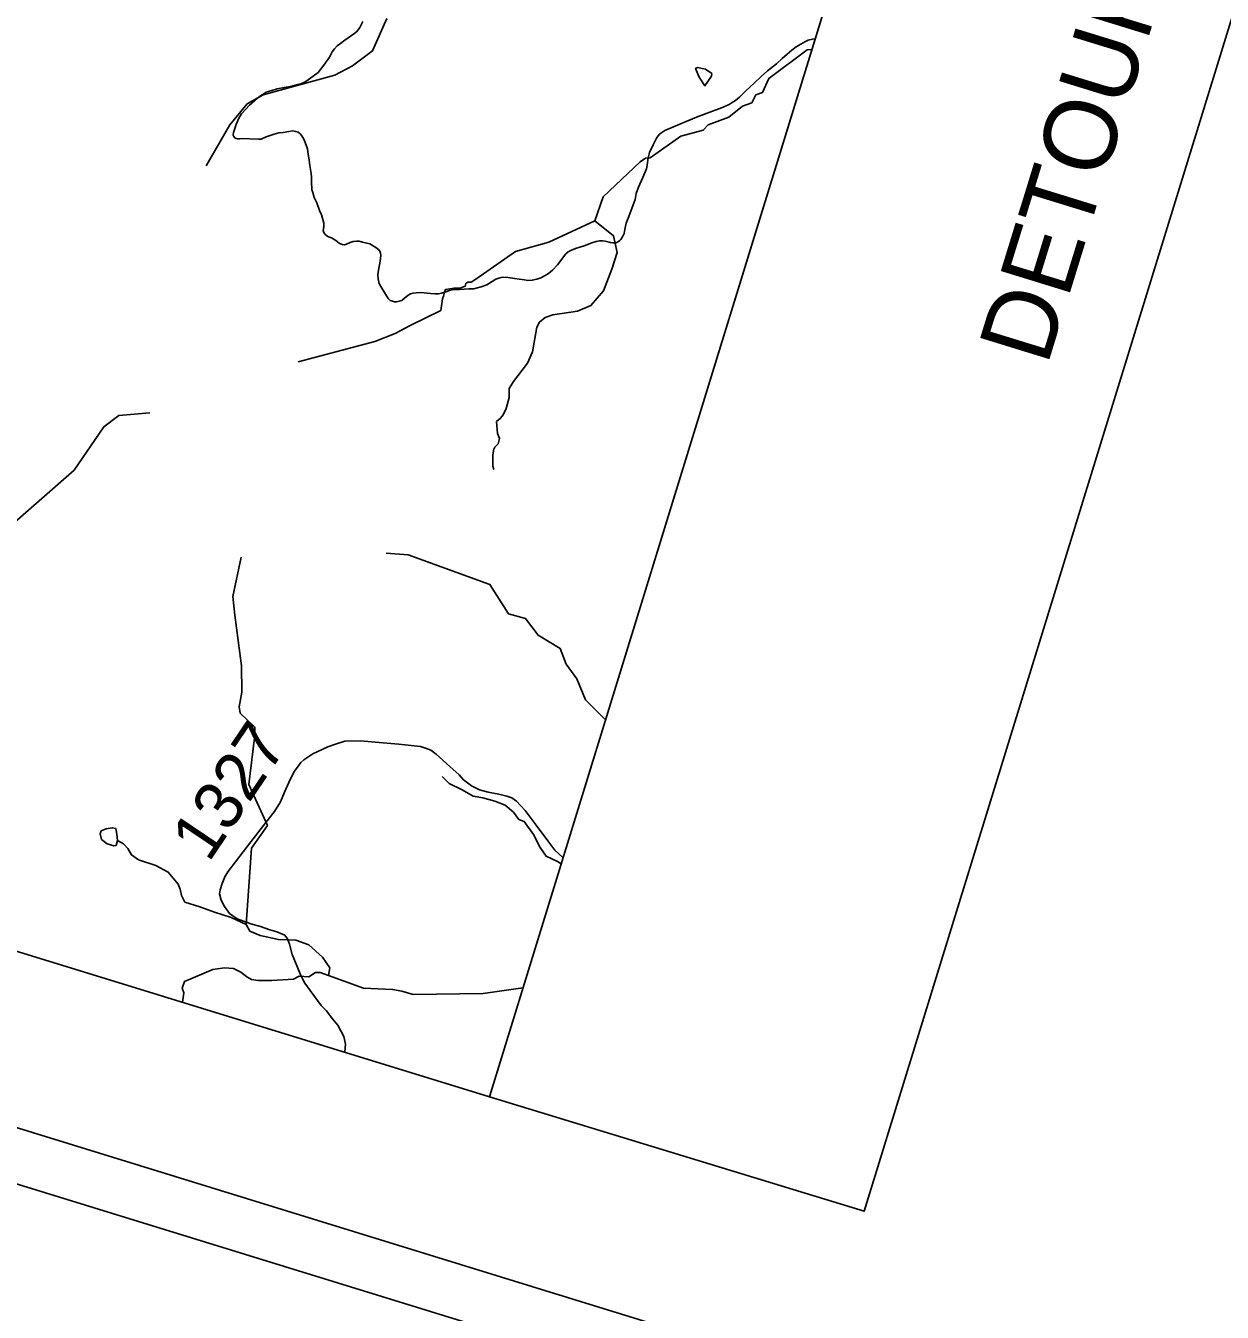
# Model space of a CAD drawing. Extents: x 1347947 to 1350662, y 1027710 to 1030532.
# Drawn here: x 1348242 to 1348353.5, y 1028682.4 to 1028802.3 of the extents above; entities that cross this region are included whole.
import ezdxf

# ---------------------------------------------------------------- set-up
doc = ezdxf.new("R2010")
doc.units = 0
for name, color, linetype in [('Default', 7, 'Continuous'), ('Prop Leader Line Light', 7, 'Continuous'), ('Prop WCC CELL', 7, 'Continuous'), ('Sheet Title CELL', 7, 'Continuous')]:
    doc.layers.add(name, color=color, linetype=linetype)

msp = doc.modelspace()

# ---------------------------------------------------------------- linework, layer by layer
at = {"layer": 'Default'}
msp.add_line((1348274.57, 1028772.86), (1348267.42, 1028770.97), dxfattribs=at)
for points in [[(1348258.85, 1028789.21), (1348261.05, 1028793.03), (1348262.68, 1028795.01), (1348264.17, 1028795.84), (1348270.83, 1028797.68), (1348272.49, 1028798.54), (1348274.35, 1028799.93), (1348275.67, 1028802.95)], [(1348273.43, 1028802.68), (1348273.17, 1028802.12), (1348272.92, 1028801.75), (1348272.71, 1028801.58), (1348271.76, 1028800.93), (1348271.37, 1028800.63), (1348271.06, 1028800.39), (1348270.8, 1028800.11), (1348270.6, 1028799.83), (1348270.33, 1028799.35), (1348269.8, 1028798.6), (1348269.27, 1028797.91), (1348268.49, 1028797.31), (1348268.24, 1028797.14), (1348267.89, 1028796.95), (1348267.66, 1028796.87), (1348267.36, 1028796.8), (1348266.71, 1028796.62), (1348266.13, 1028796.53), (1348265.48, 1028796.38), (1348264.89, 1028796.2), (1348264.44, 1028796.07), (1348264.08, 1028795.85), (1348263.82, 1028795.69), (1348263.38, 1028795.31), (1348262.9, 1028794.86), (1348262.15, 1028794.07), (1348261.88, 1028793.66), (1348261.65, 1028793.07), (1348261.4, 1028792.32), (1348261.37, 1028792.14), (1348261.38, 1028792.07), (1348261.44, 1028791.96), (1348261.52, 1028791.82), (1348261.63, 1028791.78), (1348261.76, 1028791.75), (1348261.98, 1028791.75)], [(1348296.39, 1028782.11), (1348296.48, 1028782.09), (1348296.74, 1028782.06), (1348297.04, 1028782.05), (1348297.27, 1028782.16), (1348297.39, 1028782.26), (1348297.47, 1028782.35), (1348297.65, 1028782.6), (1348297.78, 1028782.93), (1348297.86, 1028783.3), (1348297.9, 1028783.59), (1348297.98, 1028783.87), (1348298.22, 1028784.51), (1348298.64, 1028785.59), (1348298.8, 1028786.07), (1348298.91, 1028786.63), (1348299.14, 1028787.22), (1348299.54, 1028788.14), (1348299.88, 1028788.93), (1348299.94, 1028789.29), (1348300.04, 1028789.98), (1348300.15, 1028790.47), (1348300.49, 1028791.19), (1348300.81, 1028791.8), (1348301.04, 1028792.13), (1348301.29, 1028792.34), (1348301.58, 1028792.52), (1348302.39, 1028792.86), (1348303.58, 1028793.36), (1348304.54, 1028793.74), (1348305.77, 1028794.23), (1348306.87, 1028794.63), (1348307.57, 1028794.94), (1348307.86, 1028795.11), (1348308.16, 1028795.32), (1348308.53, 1028795.62), (1348309.11, 1028796.21), (1348309.89, 1028796.93), (1348310.54, 1028797.55), (1348311.14, 1028798.06), (1348311.98, 1028798.71), (1348312.52, 1028799.22), (1348312.96, 1028799.62), (1348313.41, 1028800), (1348313.82, 1028800.3), (1348314.26, 1028800.57), (1348314.68, 1028800.81), (1348314.94, 1028800.92), (1348315.32, 1028801.01), (1348315.58, 1028801.04)], [(1348315.28, 1028800.07), (1348314.83, 1028800.03), (1348311.27, 1028797.37), (1348310.69, 1028796.05), (1348310.06, 1028795.83), (1348309.67, 1028795.08), (1348308.82, 1028794.77), (1348307.53, 1028793.75), (1348305.63, 1028793.03), (1348305.14, 1028792.55), (1348303.08, 1028792), (1348300.22, 1028789.98), (1348299.79, 1028789.95), (1348299.28, 1028789.59), (1348295.83, 1028786.34), (1348295.05, 1028784.1), (1348290.78, 1028782.11), (1348287.67, 1028781.24), (1348283.96, 1028778.66), (1348283.53, 1028778.39), (1348283.22, 1028778.37), (1348283.04, 1028778.27), (1348282.98, 1028778.02), (1348282.58, 1028777.86), (1348281.95, 1028777.84), (1348281.14, 1028777.69), (1348281.04, 1028777.44)], [(1348305.92, 1028797.58), (1348305.32, 1028796.67), (1348304.77, 1028797.48), (1348304.44, 1028798.3), (1348304.62, 1028798.39), (1348305.37, 1028798.22), (1348305.96, 1028797.81), (1348305.92, 1028797.58)], [(1348305.92, 1028797.58), (1348305.32, 1028796.67), (1348304.77, 1028797.48), (1348304.44, 1028798.3), (1348304.62, 1028798.39), (1348305.37, 1028798.22), (1348305.96, 1028797.81), (1348305.92, 1028797.58)], [(1348261.98, 1028791.75), (1348262.28, 1028791.76), (1348262.92, 1028791.74), (1348263.75, 1028791.69), (1348263.98, 1028791.72), (1348264.45, 1028791.92), (1348265.17, 1028792.16), (1348265.61, 1028792.29), (1348266.01, 1028792.34), (1348266.54, 1028792.41), (1348266.89, 1028792.48), (1348267.2, 1028792.43), (1348267.42, 1028792.35), (1348267.62, 1028792.19), (1348267.77, 1028792.02), (1348267.96, 1028791.71), (1348268.08, 1028791.41), (1348268.29, 1028790.79), (1348268.34, 1028790.29), (1348268.45, 1028789.79), (1348268.49, 1028789.48), (1348268.51, 1028789.26), (1348268.63, 1028788.5), (1348268.65, 1028788.18), (1348268.67, 1028787.51), (1348268.7, 1028787.22), (1348268.68, 1028787), (1348268.79, 1028786.73), (1348268.91, 1028786.28), (1348269.17, 1028785.77), (1348269.4, 1028785.05), (1348269.59, 1028784.66), (1348269.73, 1028784.22), (1348269.81, 1028783.88), (1348269.82, 1028783.55), (1348269.75, 1028783.21), (1348269.77, 1028783.09), (1348269.85, 1028782.95), (1348270.01, 1028782.76), (1348270.24, 1028782.62), (1348270.53, 1028782.5), (1348270.85, 1028782.32), (1348271.05, 1028782.18), (1348271.28, 1028781.98), (1348271.56, 1028781.88), (1348271.73, 1028781.86), (1348271.92, 1028781.91), (1348272.26, 1028782.09), (1348272.56, 1028782.17), (1348272.85, 1028782.19), (1348273.09, 1028782.19), (1348273.42, 1028782.12), (1348274.09, 1028781.94), (1348274.66, 1028781.61), (1348274.91, 1028781.42), (1348275.04, 1028781.26), (1348275.1, 1028781.1), (1348275.11, 1028780.91), (1348275.05, 1028780.34), (1348274.9, 1028779.51), (1348274.85, 1028779.07), (1348274.87, 1028778.69), (1348274.97, 1028778.27), (1348275.12, 1028777.97), (1348275.57, 1028777.26), (1348275.82, 1028776.86), (1348275.98, 1028776.69), (1348276.2, 1028776.61), (1348276.39, 1028776.56), (1348276.57, 1028776.54), (1348276.83, 1028776.6), (1348277.08, 1028776.69), (1348277.33, 1028776.88), (1348277.67, 1028777.16), (1348277.9, 1028777.29), (1348278.12, 1028777.36), (1348278.41, 1028777.39), (1348278.86, 1028777.41), (1348279.76, 1028777.32), (1348280.19, 1028777.29), (1348280.49, 1028777.3), (1348280.77, 1028777.35), (1348281.08, 1028777.44), (1348281.52, 1028777.62), (1348281.9, 1028777.69), (1348282.45, 1028777.69), (1348283.33, 1028777.75), (1348283.79, 1028777.77), (1348284, 1028777.82), (1348284.48, 1028777.95), (1348285, 1028778.15), (1348285.5, 1028778.46), (1348285.85, 1028778.67), (1348286.1, 1028778.77), (1348286.34, 1028778.83), (1348286.58, 1028778.85), (1348286.97, 1028778.81), (1348287.57, 1028778.74), (1348288.5, 1028778.59), (1348288.83, 1028778.55), (1348289.22, 1028778.57), (1348289.67, 1028778.66), (1348290.04, 1028778.79), (1348290.44, 1028779.01), (1348290.73, 1028779.18), (1348291.1, 1028779.5), (1348291.57, 1028779.99), (1348291.99, 1028780.52), (1348292.34, 1028781), (1348292.57, 1028781.21), (1348292.88, 1028781.38), (1348293.27, 1028781.53), (1348294.07, 1028781.77), (1348294.79, 1028782.06), (1348295.18, 1028782.17), (1348295.49, 1028782.23), (1348295.76, 1028782.22), (1348296.03, 1028782.19), (1348296.39, 1028782.11)], [(1348295.05, 1028784.1), (1348296.8, 1028782.71), (1348297.14, 1028781.16), (1348296.63, 1028779.6), (1348295.85, 1028777.59), (1348294.69, 1028776.21), (1348293.43, 1028775.69), (1348291.16, 1028775.34), (1348290.42, 1028775.09), (1348289.91, 1028774.66), (1348289.64, 1028774.18), (1348289.25, 1028771.91), (1348288.8, 1028770.85), (1348287.49, 1028769.14), (1348287.09, 1028768.48)], [(1348281.04, 1028777.44), (1348280.95, 1028777.09), (1348280.86, 1028776.82), (1348280.71, 1028775.74), (1348277.86, 1028774.34), (1348276.46, 1028773.59), (1348274.57, 1028772.86)], [(1348287.09, 1028768.48), (1348287.07, 1028767.65), (1348286.8, 1028766.61), (1348286.53, 1028766.03), (1348286.28, 1028765.71), (1348285.9, 1028765.4), (1348285.98, 1028764.29), (1348286.18, 1028763.81), (1348286.06, 1028763.34), (1348285.74, 1028763.01), (1348285.64, 1028762.84), (1348285.55, 1028762.3), (1348285.55, 1028761.48), (1348285.56, 1028761.23), (1348285.66, 1028760.93)], [(1348253.6, 1028766.22), (1348250.7, 1028765.96), (1348249.33, 1028764.92), (1348246.56, 1028760.88), (1348239.77, 1028754.93)], [(1348296.05, 1028737.63), (1348294.19, 1028739.49), (1348293.38, 1028741.45), (1348292.39, 1028742.81), (1348291.84, 1028744.27), (1348289.77, 1028745.49), (1348288.61, 1028747.04), (1348287.01, 1028747.48), (1348285.28, 1028750.23), (1348277.68, 1028753), (1348275.62, 1028753.13)], [(1348270.38, 1028714.51), (1348269.69, 1028715.51), (1348268.41, 1028716.65), (1348267.19, 1028717.08), (1348265.58, 1028717.15), (1348263.89, 1028717.54), (1348262.92, 1028717.94), (1348262.58, 1028718.55), (1348263.06, 1028725.66), (1348264.55, 1028727.76), (1348262.81, 1028731.6), (1348263.35, 1028735.94), (1348263.37, 1028736.94), (1348262.01, 1028738.25), (1348261.92, 1028738.82), (1348262.16, 1028740.19), (1348262.15, 1028742.65), (1348261.52, 1028747.38), (1348261.35, 1028749.09), (1348262.12, 1028752.78)], [(1348288.57, 1028729.17), (1348287.77, 1028730.04), (1348287.32, 1028730.34), (1348286.86, 1028730.51), (1348286.1, 1028730.7), (1348285.13, 1028730.88), (1348284.32, 1028731.09), (1348283.56, 1028731.46), (1348282.83, 1028732.03), (1348282.43, 1028732.48), (1348281.54, 1028733.28), (1348280.28, 1028734.42), (1348279.77, 1028734.79), (1348279.29, 1028734.99), (1348278.81, 1028735.12), (1348276.79, 1028735.35), (1348274.6, 1028735.55), (1348273.22, 1028735.65), (1348271.76, 1028735.63), (1348270.9, 1028735.34), (1348270.19, 1028735.09), (1348268.79, 1028734.46), (1348267.94, 1028733.89), (1348267.66, 1028733.64), (1348267.45, 1028733.33), (1348267.05, 1028732.8), (1348266.54, 1028731.79), (1348266.15, 1028730.89), (1348265.76, 1028729.99), (1348265.21, 1028729.09), (1348264.4, 1028728.05), (1348263, 1028726.26), (1348260.87, 1028723.45), (1348260.59, 1028722.99), (1348260.33, 1028722.36), (1348260.14, 1028721.77), (1348260.08, 1028721.4), (1348260.26, 1028720.81), (1348260.55, 1028720.24), (1348261.03, 1028719.58), (1348261.74, 1028719.09), (1348263.02, 1028718.61), (1348263.9, 1028718.35), (1348264.79, 1028718.05), (1348265.44, 1028717.86), (1348266.17, 1028717.57), (1348266.42, 1028717.23), (1348266.61, 1028716.72), (1348266.86, 1028715.76), (1348267.32, 1028714.64), (1348267.67, 1028713.81), (1348268.05, 1028713.09), (1348268.54, 1028712.41), (1348269.57, 1028711.02), (1348270.06, 1028710.52), (1348270.59, 1028709.79), (1348271.13, 1028709.16), (1348271.69, 1028708.13), (1348271.84, 1028707.4), (1348271.76, 1028706.7), (1348271.75, 1028706.66)], [(1348280.83, 1028732.33), (1348281.48, 1028731.69), (1348282.7, 1028731.1), (1348283.72, 1028730.5), (1348284.62, 1028730.35), (1348285.74, 1028730.05), (1348286.69, 1028729.66), (1348287.48, 1028729.02), (1348287.99, 1028728.33), (1348288.49, 1028728.13), (1348289.33, 1028726.92), (1348289.95, 1028725.72), (1348290.52, 1028724.91), (1348291.58, 1028724.43), (1348291.91, 1028724.2)], [(1348292.09, 1028724.79), (1348291.32, 1028725.48), (1348290.68, 1028726.33), (1348289.59, 1028727.79), (1348288.57, 1028729.17)], [(1348250.58, 1028726.38), (1348250.54, 1028726.96), (1348250.42, 1028727.49), (1348250.1, 1028727.57), (1348249.53, 1028727.46), (1348249.08, 1028727.27), (1348248.99, 1028727), (1348249.09, 1028726.47), (1348249.62, 1028726.08), (1348250.26, 1028725.88), (1348250.46, 1028725.91), (1348250.58, 1028726.38)], [(1348250.58, 1028726.38), (1348250.54, 1028726.96), (1348250.42, 1028727.49), (1348250.1, 1028727.57), (1348249.53, 1028727.46), (1348249.08, 1028727.27), (1348248.99, 1028727), (1348249.09, 1028726.47), (1348249.62, 1028726.08), (1348250.26, 1028725.88), (1348250.46, 1028725.91), (1348250.58, 1028726.38)], [(1348250.58, 1028726.38), (1348251.15, 1028726.08), (1348251.54, 1028725.63), (1348251.91, 1028725.03), (1348252.55, 1028724.56), (1348254.17, 1028724.06)], [(1348254.17, 1028724.06), (1348255.32, 1028723.43), (1348256.25, 1028722.3), (1348256.43, 1028721.83), (1348256.54, 1028721.26), (1348256.87, 1028720.64), (1348258.25, 1028720.21), (1348259.62, 1028719.71), (1348261.17, 1028719.19), (1348262.58, 1028718.55)], [(1348256.65, 1028711.31), (1348256.78, 1028712.2), (1348256.6, 1028712.61), (1348256.82, 1028713.25), (1348259.48, 1028714.37), (1348260.55, 1028714.51), (1348261.39, 1028714.46), (1348262.08, 1028714.11), (1348262.64, 1028713.67), (1348263.06, 1028713.42), (1348263.71, 1028713.34), (1348264.98, 1028713.32), (1348266.98, 1028713.47), (1348267.52, 1028713.75), (1348268.42, 1028713.68), (1348269.03, 1028714.08), (1348269.47, 1028714.07), (1348270.25, 1028713.79)], [(1348288.36, 1028712.66), (1348284.65, 1028712.12), (1348278.12, 1028712.02), (1348277.08, 1028712.35), (1348276.22, 1028712.51), (1348273.52, 1028712.62), (1348270.25, 1028713.79), (1348270.38, 1028714.51)]]:
    msp.add_lwpolyline(points, dxfattribs=at)
at = {"layer": 'Prop WCC CELL'}
for p, q in [((1348285.23, 1028702.5), (1348393.41, 1029053.78)), ((1348067.18, 1028769.65), (1348285.23, 1028702.5))]:
    msp.add_line(p, q, dxfattribs=at)
msp.add_lwpolyline([(1348285.23, 1028702.5), (1348393.41, 1029053.78), (1348428.36, 1029043.07), (1348320.15, 1028691.84)], close=True, dxfattribs=at)
at = {"layer": 'Sheet Title CELL'}
for p, q in [((1348848.45, 1028512.61), (1348050.43, 1028758.36)), ((1349023.78, 1028453.38), (1348048.96, 1028753.59))]:
    msp.add_line(p, q, dxfattribs=at)

# ---------------------------------------------------------------- texts
at = {"layer": 'Prop Leader Line Light'}
for s, height, rotation, p in [('DETOUR ROUTE', 6.75, 72.8834, (1348337.19, 1028770.5)), ('1327', 4.5, 56.007, (1348259.08, 1028724.24))]:
    msp.add_text(s, height=height, rotation=rotation, dxfattribs=at).set_placement(p)
at = {"layer": 'Sheet Title CELL'}
msp.add_text('TIP PROJECT: B-4701', height=25, rotation=162.8834, dxfattribs=at).set_placement((1348484.77, 1028607.46))

doc.saveas('drawing.dxf')
